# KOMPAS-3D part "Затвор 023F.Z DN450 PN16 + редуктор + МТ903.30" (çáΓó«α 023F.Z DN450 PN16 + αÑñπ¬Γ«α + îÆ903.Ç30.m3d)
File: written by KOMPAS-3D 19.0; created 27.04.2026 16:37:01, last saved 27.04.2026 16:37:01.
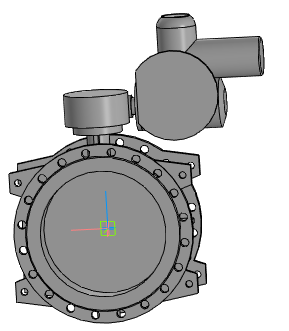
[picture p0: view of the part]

Document properties: Полное имя файла: ..\..\Затвор 023F.Z DN400-DN1600 + редуктор + МТ903\Затвор 023F.Z DN450 PN16 + редуктор + МТ903.А30.a3d

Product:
- Part/product: Затвор 023F.Z DN450 PN16 + редуктор + МТ903.30
    Масса: 410.057

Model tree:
1. Операция без истории:1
